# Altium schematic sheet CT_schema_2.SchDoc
size 357 x 214 mm
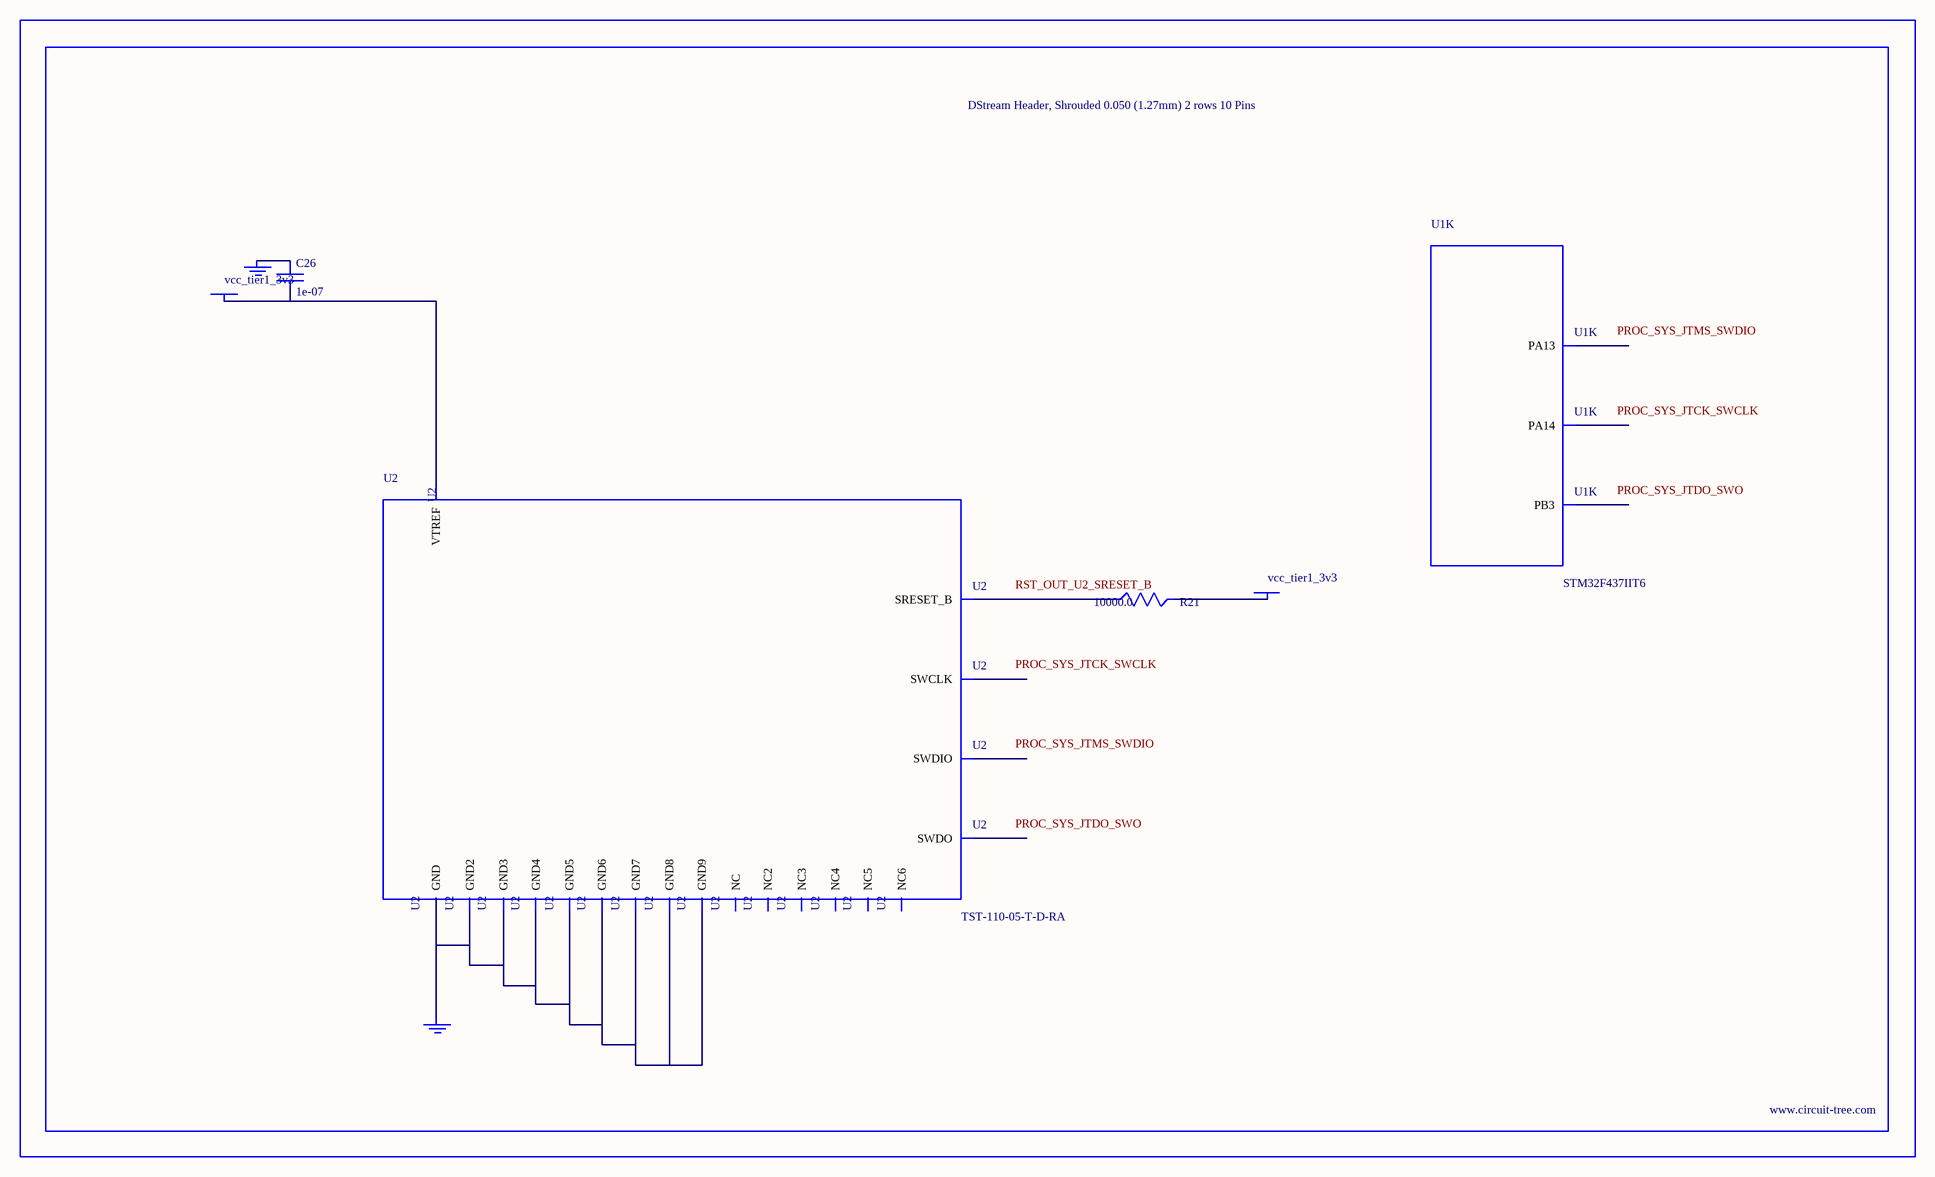
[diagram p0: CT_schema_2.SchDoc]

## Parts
BORDER1  (no value)
C26  1e-07  [C0402]
GND_INSTANCE_1_0  (no value)
GND_INSTANCE_1_1  (no value)
POWER_INSTANCE_1_0  vcc_tier1_3v3
POWER_INSTANCE_1_1  vcc_tier1_3v3
R21  10000.0  [R0603]
U1  STM32F437IIT6  [LQFP176]  (part K of 16)
U2  TST-110-05-T-D-RA  [TST-110-05-T-D-RA]

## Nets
NetC26_1: C26.1 GND_INSTANCE_1_0.0(GND)
NetC26_2: C26.2 POWER_INSTANCE_1_0.0(PWR) U2.1(VTREF)
NetGND_INSTANCE_1_1_0: GND_INSTANCE_1_1.0(GND) U2.4(GND) U2.6(GND2) U2.8(GND3) U2.10(GND4) U2.12(GND5) U2.14(GND6) U2.16(GND7) U2.18(GND8) U2.20(GND9)
NetPOWER_INSTANCE_1_1_0: POWER_INSTANCE_1_1.0(PWR) R21.2
NetR21_1: R21.1 U2.15(SRESET_B)

Not connected (* = marked no-connect by the designer): U1 124(PA13) 137(PA14) 161(PB3); U2 2(NC) 3(NC2) 5(NC3) 7(SWDIO) 9(SWCLK) 11(NC4) 13(SWDO) 17(NC5) 19(NC6)

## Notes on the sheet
- Labels drawn without touching a wire or pin: PROC_SYS_JTCK_SWCLK, PROC_SYS_JTDO_SWO, PROC_SYS_JTMS_SWDIO, RST_OUT_U2_SRESET_B

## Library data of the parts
BORDER1 = BORDER_PAGE1
C26 = C0402C104K3RACTU
GND_INSTANCE_1_0 GND_INSTANCE_1_1 = GND
POWER_INSTANCE_1_0 POWER_INSTANCE_1_1 = PWR
R21 = RC0603JR-0710KL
